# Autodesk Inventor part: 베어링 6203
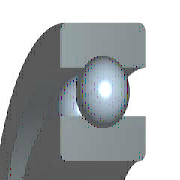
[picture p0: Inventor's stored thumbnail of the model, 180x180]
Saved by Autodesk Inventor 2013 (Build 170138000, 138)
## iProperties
IsCustomPart: 0
Company: 한국ATC센터
Created: 2014-08
Part Number: 베어링 6203
Material: 강, 연강
Description: 깊은 그루브 볼 베어링
Document SubType Name: Modeling
Standard: KS B 2023
Designer: KYOUNG IL JANG
Standards Organization: KS
Language: ko-KR
Size Designation: 6203 - 17 x 40 x 12
Categories: <MemberInstance><Categories><Category DisplayName="샤프트 부품" InternalName="7f7aeb1f-a693-4053-b835-cee3144e0d98" Mnemonic="SHFT"><Category DisplayName="베어링" Inter
Density: 1 g/cm^3
Author: KYOUNG IL JANG
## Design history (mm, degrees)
sketch "스케치" dims "d0" = 5.98 (= -0.26 x WD + 0.26 x BD)
  geometry: L1 (3.01, 14.25)-(8.99, 14.25); L2 (6, 14.25)-(6, 11.26); L3 (6, 14.25)-(6, 17.24); L4 (3.778, 12.249)-(0, 12.249); L5 (0, 8.5)-(12, 8.5); L6 (3.778, 16.251)-(0, 16.251); L7 (0, 20)-(12, 20); L8 (12, 8.5)-(12, 12.249); L9 (8.222, 12.249)-(12, 12.249); L10 (8.222, 16.251)-(12, 16.251); L11 (12, 20)-(12, 16.251); L12 (-1.4, 0)-(8.4, 0) reference; L13 (0, -0.3)-(0, 5.3) reference
  constraints: 22 end point, 4 point on line, 2 collinear, 2 perpendicular, 2 symmetric about line, 1 midpoint, 1 parallel, 14 other
  dimensions: "d9" = 17 diameter of L5 L12 (= WD); "d11" = 40 diameter of L7 L12 (= BD); "d12" = 12 distance between parallel lines of L8 L13 (= KB); "d13" = 24.498 diameter of L9 L12 (= 0.326 x BD + 0.674 x WD)
revolve "본체" stored, may be unused: angle "d6" = 90 deg
revolve "볼" stored, may be unused: angle "d7" = 90 deg
pattern_circular "IDS_ARRAYBALL[SIMPL:T]" dims angle "d3" = 360 deg
body "Solid1"
fillet "모깎기1" dims "d1" = 0.6 (= KRS)
other parameters: "WD" = 17 [user parameter; used in 5 equation terms], "BD" = 40 [user parameter; used in 5 equation terms], "KB" = 12 [user parameter; used in 1 equation term], "KRS" = 0.6 [user parameter; used in 1 equation term], "d4" = 0, "d5" = 0, "d8" = 0, "d14" = 0, "d15" = 0, "BBA" = 0 [user parameter], "BC0" = 4750000 [user parameter], "BC" = 9560000 [user parameter], "WR" = 8.5 (= 0.5 x WD) [user parameter]
